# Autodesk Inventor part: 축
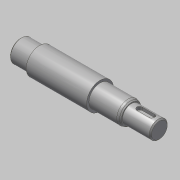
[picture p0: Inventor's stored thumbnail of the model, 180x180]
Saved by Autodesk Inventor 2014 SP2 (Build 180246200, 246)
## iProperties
Created: 2016-06
Part Number: 축
Material: 강철, 연강
Document SubType Name: Modeling
Designer: mduedu
Density: 7.86 g/cm^3
Appearance: 강철
Author: mduedu
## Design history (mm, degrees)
sketch "스케치1"
  geometry: L1 (-62, 0)-(62, 0); L2 (-62, 0)-(-62, 10); L3 (-62, 10)-(-45, 10); L4 (-45, 10)-(-45, 12); L5 (-45, 12)-(9, 12); L6 (9, 12)-(9, 10); L7 (9, 10)-(37, 10); L8 (37, 10)-(37, 8); L9 (37, 8)-(62, 8); L10 (62, 8)-(62, 0); 2 further points
  constraints: 20 end point, 5 parallel, 2 perpendicular, 1 coincident, 1 collinear, 1 horizontal, 1 midpoint, 1 vertical
  dimensions: "d0" = 124 distance of L1.start L1.end; "d2" = 16 diameter of L9 L1; "d3" = 20 diameter of L7 L1; "d4" = 24 diameter of L5 L1; "d5" = 20 diameter of L3 L1; "d6" = 17 distance of L2.end L3.end; "d7" = 25 distance of L8.end L9.end; "d8" = 53 distance from line of L5.end L10
revolve "회전1" sketch "스케치1" stored, may be unused: angle "d9" = 90 deg
chamfer "모따기1" distance "d10" = 2; stored, may be unused: second distance "d11" = 2, angle "d12" = 30 deg
fillet "모깎기1" dims "d13" = 4
node "작업 평면1"
sketch "스케치2"
  geometry: L1 (-5, 2.5)-(6, 2.5); L2 (6, -2.5)-(-5, -2.5); L3 (-5, 0)-(6, 0); L4 (-12.5, 8.845)-(-12.5, -8.845) reference; A1 r 2.5 centre (-5, 0) between (-5, 2.5) and (-5, -2.5); A2 r 2.5 centre (6, 0) between (6, -2.5) and (6, 2.5); 1 further point
  constraints: 6 end point, 4 point on circle, 3 tangent, 2 centre point, 2 parallel, 1 horizontal, 1 horizontal alignment
  dimensions: "d14" = 5 distance edge to line of A1 L4; "d15" = 5 distance between parallel lines of L2 L1; "d16" = 16 dimension on A2 A1
extrude "돌출1" cut sketch "스케치2" distance "d17" = 3; taper "d18" = 0 deg
chamfer "모따기2" distance "d19" = 1; stored, may be unused: second distance "d20" = 2, angle "d21" = 30 deg
sketch "스케치3"
  geometry: L1 (-37, -8)-(-61, -8) reference; L2 (-62, -7)-(-62, 7) reference; L3 (-38.5, -8)-(-40, -6.5); L4 (-40, -6.5)-(-40, -8); L5 (-38.5, -8)-(-40, -8); 1 further point
  constraints: 6 end point, 2 point on line, 1 collinear, 1 vertical
  dimensions: "d22" = 45 deg angle of L4 L3; "d23" = 22 distance between parallel lines of L2 L4; "d24" = 3 diameter of L3.start L4
revolve "회전2" stored, may be unused: angle "d25" = 90 deg
node "작업점1"
sketch "스케치4"
  geometry: 1 further point
hole "구멍1" sketch "스케치4" at (0, 0) diameter "d26" = 3.242; stored, may be unused: countersink angle "d30" = 90 deg, drill point angle "d32" = 120 deg; dims "d27" = 8, "d28" = 4, "d29" = 2, "d31" = 11
chamfer "모따기3" distance "d33" = 2; stored, may be unused: second distance "d34" = 2, angle "d35" = 30 deg
node "솔리드1"
